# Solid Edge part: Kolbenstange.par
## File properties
Username: bmolnar
Dokumentum tartalom típus: 0
Author: bmolnar
Last saved by: bmolnar
Revision: 79
Sűrűség: 0,000 kg/m^3
Pontosság: 0,990
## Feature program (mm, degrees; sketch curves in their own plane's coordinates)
base feature "unnamed BaseFeature 1"
sketch for "unnamed Protrusion 1" plane through (29.4, 0.0012, 0) normal (1, 0, 0) x-axis (0, -1, 0)
  circle centre (0.0012, 0) radius 12.5
extrude "unnamed Protrusion 1" add finite 15.9 along +normal
sketch for "Kihúzás_3" #1 plane through (29.4, 0.0012, 0) normal (1, 0, 0) x-axis (0, -1, 0)
  circle centre (0.0012, 0) radius 5
sketch for "Kihúzás_3" #2 plane through (29.4, 0.0012, 0) normal (1, 0, 0) x-axis (0, -1, 0)
  circle centre (0.0012, 0) radius 12.5
extrude "Kihúzás_3" add finite 15.2 along -normal
sketch for "Furat_1" plane through (-8, 0, 0.0012) normal (-1, 0, 0) x-axis (0, 0, -1)
hole "Furat_1" diameter 4.13 finite  VBottomAngle = 118 deg
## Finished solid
Body 1: solid body, 16 faces, 22 edges, 8 vertices.
  Faces by surface: plane 8, cylinder 4, cone 2, torus 2
  Edges by curve: circle 12, line 6, curve on surface 2, ellipse 2
Bounding box of the edges (mm; curved faces can reach further): 55.300 x 25.000 x 25.000, from (-10, -12.5, -12.5) to (45.3, 12.5, 12.5).
Cylindrical faces by radius (mm): R2.065 x1, R2.625 x1, R5 x1, R12.5 x1
Conical faces (half-angle, radius in mm at the cone's reference point): 45 deg R2.725 x1, 59 deg R2.065 x1
Toroidal faces (ring radius, tube radius in mm): R2.425 r0.2 x1, R3.7 r1.3 x1
Planar faces by outward normal: +x 1, +z 1, -x 3, -z 1, oblique 2
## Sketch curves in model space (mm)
circle centre (29.4, 0, 0) radius 12.5
circle centre (29.4, 0, 0) radius 5
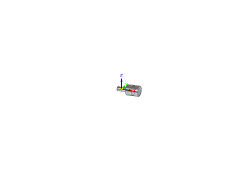
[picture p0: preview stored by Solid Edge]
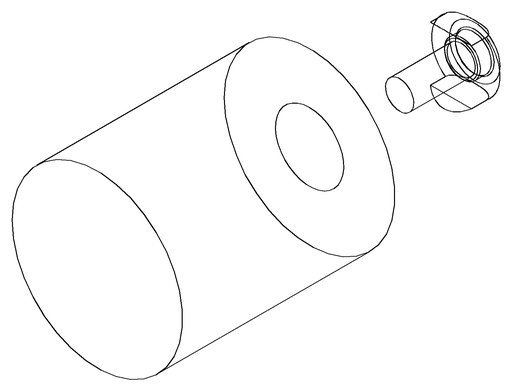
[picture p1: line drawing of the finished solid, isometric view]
